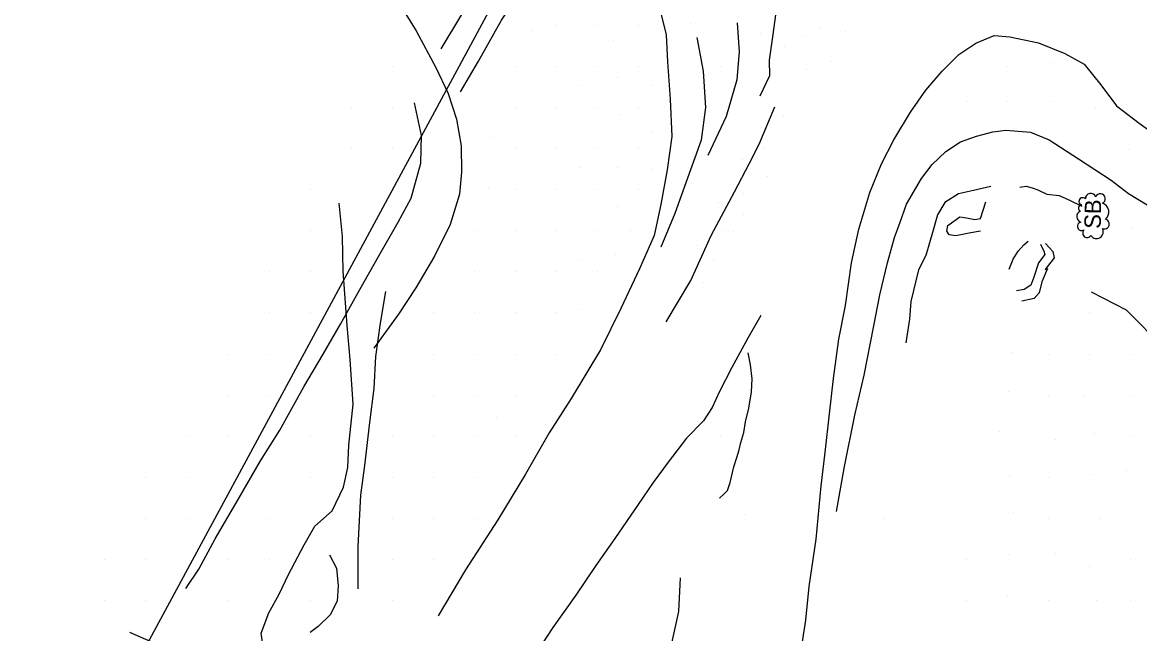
# Model space of a CAD drawing. Extents: x 19528164 to 19545171, y 7585743 to 7602745.
# Drawn here: x 19530420 to 19530964, y 7590664 to 7590962 of the extents above; entities that cross this region are included whole.
import ezdxf

# ---------------------------------------------------------------- set-up
doc = ezdxf.new("R2010")
doc.units = 0
for name, color, linetype in [('Default', 7, 'Continuous'), ('PhoBreakLine', 7, 'Continuous'), ('PhoISAEPoints', 7, 'Continuous'), ('PhoSurveyLimits', 7, 'Continuous'), ('PhoVegetation', 7, 'Continuous')]:
    doc.layers.add(name, color=color, linetype=linetype)

# ---------------------------------------------------------------- blocks, each defined once
blk = doc.blocks.new('SHRUB')
at = {"layer": 'Default'}
for centre, radius, start, end in [((-5.57, 5.14), 2.08, 10.5948, 214.3611), ((-0.81, 4.83), 2.81, 22.6036, 165.7836), ((3.27, 5.33), 1.59, 0.4605, 158.7839), ((6.61, 4.92), 1.8, 311.3936, 166.4114), ((-8.06, -2.12), 3.34, 125.8289, 299.2848), ((-8.82, 2.41), 2.18, 45.3455, 236.8073), ((8, 0.98), 2.6, 290.9039, 94.3687), ((-4.25, -5.95), 2.36, 157.0258, 349.7602), ((1.54, -3.45), 4.54, 220.0183, 343.6977), ((8.09, -3.71), 2.42, 204.8294, 69.8871)]:
    blk.add_arc(centre, radius, start, end, dxfattribs=at)
blk.add_text('SB', height=7.998, dxfattribs=at).set_placement((-6.62, -4.17))

msp = doc.modelspace()

# ---------------------------------------------------------------- linework, layer by layer
at = {"layer": 'PhoBreakLine'}
for points in [[(19530550.69, 7591170.8), (19530563.11, 7591162.21), (19530580.92, 7591148.29), (19530600.48, 7591130.16), (19530614.58, 7591114.45), (19530632.27, 7591092.51), (19530647.29, 7591073.38), (19530663.97, 7591052.42), (19530667.84, 7591042.43), (19530667.95, 7591034.18), (19530664.24, 7591022.5), (19530658.51, 7591010.63), (19530652.31, 7591000.06), (19530644.25, 7590984.42), (19530633.83, 7590965.38), (19530623.69, 7590948.7)], [(19530633.29, 7590927.79), (19530642.08, 7590942.64), (19530653.35, 7590962.66), (19530665.41, 7590981.02), (19530675.99, 7591000.09), (19530684.57, 7591014.52), (19530690.6, 7591025.66), (19530690.6, 7591025.66), (19530692.67, 7591034.39), (19530690.91, 7591042.02), (19530686.94, 7591051.91), (19530679.36, 7591060.62), (19530675.4, 7591066.27), (19530666.86, 7591077.03), (19530659.34, 7591087.61), (19530652.15, 7591095.26), (19530643.55, 7591105.89), (19530630.63, 7591119.04), (19530620.41, 7591129.76), (19530611.11, 7591138.96)], [(19530692.67, 7591034.39), (19530699.87, 7591027.21), (19530709.28, 7591011.65), (19530721.4, 7590989.7), (19530729.65, 7590971.15), (19530733.63, 7590955.63), (19530734.22, 7590942.42), (19530735.5, 7590924.2), (19530736.34, 7590906.03), (19530734.16, 7590889.81), (19530731, 7590872.82), (19530727.68, 7590857.77), (19530720.64, 7590841.48), (19530711.53, 7590822.22), (19530701.58, 7590802.09), (19530687.32, 7590778.37), (19530676.57, 7590761.63), (19530665.03, 7590741.43), (19530651.51, 7590719.23), (19530635.74, 7590694.91), (19530622.44, 7590672.51)], [(19530603.02, 7590971.6), (19530611.71, 7590957.55), (19530621.26, 7590939.63), (19530627.37, 7590926.96), (19530631.44, 7590914.42), (19530633.66, 7590901.52), (19530633.81, 7590888.67), (19530632.93, 7590877.92), (19530628.32, 7590863.06), (19530620.65, 7590847.69), (19530611.64, 7590832.33), (19530603.13, 7590819.45), (19530591.06, 7590802.78)], [(19530786.93, 7590965.34), (19530785.58, 7590955.69), (19530783.89, 7590943.27), (19530783.93, 7590935.51), (19530779.32, 7590925.7)], [(19530754.12, 7590896.86), (19530763, 7590915.96), (19530768.21, 7590933.75), (19530769.36, 7590947.2), (19530768.39, 7590961.41)], [(19530748.62, 7590954.23), (19530751.66, 7590937.8), (19530752.84, 7590920.14), (19530750.62, 7590904.23), (19530747.63, 7590895.58), (19530744.06, 7590885.65), (19530737.75, 7590868.44), (19530730.99, 7590852.13)], [(19530801.67, 7590670.26), (19530803.32, 7590686.66), (19530806.75, 7590709.84), (19530809.24, 7590735.8), (19530811.13, 7590752.07), (19530813.26, 7590770.88), (19530815.11, 7590788.12), (19530817.73, 7590807.17), (19530821.01, 7590823.57), (19530823.98, 7590844.49), (19530827.55, 7590860.78), (19530832.89, 7590878.68), (19530838.55, 7590892.74), (19530844.52, 7590904.43), (19530852.63, 7590917.85), (19530860.23, 7590928.59), (19530868.18, 7590937.88), (19530876.22, 7590945.95), (19530884.51, 7590951.51), (19530893.52, 7590955.16), (19530901.17, 7590954.53), (19530915.14, 7590951.61), (19530927.98, 7590946.47), (19530937.44, 7590941.18), (19530945.56, 7590931.19), (19530953.13, 7590920.9), (19530964.13, 7590912.57), (19530975.99, 7590904.09)], [(19530499.44, 7590685.8), (19530505.76, 7590695.14), (19530513.81, 7590710), (19530525.03, 7590729.1), (19530535.88, 7590747.99), (19530545.23, 7590762.95), (19530557.05, 7590783.96), (19530566.32, 7590799.91), (19530574.83, 7590814.55), (19530584.21, 7590831.49), (19530593.42, 7590847.47), (19530602.92, 7590864.28), (19530609.26, 7590875.91), (19530614.07, 7590893.07), (19530614.38, 7590906.42), (19530610.94, 7590922.47)], [(19530733.61, 7590815.67), (19530745.69, 7590835.86), (19530755.61, 7590857.82), (19530766.91, 7590879.08), (19530774.15, 7590892.97), (19530778.96, 7590902.18), (19530786.56, 7590920.5)], [(19530816.59, 7590723.23), (19530820.58, 7590745.21), (19530825.54, 7590770.15), (19530830.14, 7590789.72), (19530834.86, 7590813.79), (19530837.77, 7590828.8), (19530841.53, 7590844.47), (19530844.83, 7590856.84), (19530847.71, 7590864.21), (19530850.81, 7590872.95), (19530858.06, 7590885.57), (19530863.23, 7590892.36), (19530869.89, 7590898.62), (19530877.05, 7590903.34), (19530884.94, 7590906.2), (19530892.89, 7590908.35), (19530899.15, 7590909.14), (19530911.25, 7590908.18), (19530920.26, 7590904.3), (19530934.68, 7590895.09), (19530950.49, 7590884.76), (19530959.02, 7590878.21), (19530968.04, 7590872.67)], [(19530891.82, 7590881.61), (19530883.36, 7590879.75), (19530876.13, 7590878.01), (19530869.39, 7590873.91), (19530865.95, 7590867.8), (19530863.41, 7590859.2), (19530860.19, 7590847.99), (19530856.65, 7590841.02), (19530852.82, 7590825.57), (19530852.16, 7590816.92), (19530850.42, 7590805.38)], [(19530906.01, 7590881.29), (19530909.06, 7590881.78), (19530911.95, 7590881), (19530914.71, 7590880.03), (19530919.14, 7590877.96), (19530925.14, 7590877.24), (19530929.87, 7590875.16), (19530936.18, 7590872.08)], [(19530472.05, 7590664.5), (19530496.5, 7590653.83), (19530522.37, 7590642.56), (19530534.31, 7590636.88), (19530537.81, 7590638.52), (19530537.87, 7590646.74), (19530537.41, 7590655.3), (19530536.22, 7590663.95), (19530539.98, 7590673.97), (19530544.88, 7590683.06), (19530549.56, 7590692.64), (19530557.15, 7590706.97), (19530562.37, 7590716.2), (19530570.71, 7590723.65), (19530576.39, 7590735.16), (19530578.47, 7590744.68), (19530578.98, 7590755.65), (19530580.97, 7590775.5), (19530579.51, 7590797.29), (19530578.04, 7590813.85), (19530576.14, 7590840.39), (19530575.81, 7590857.29), (19530574.2, 7590873.5)], [(19530886.78, 7590859.92), (19530882.12, 7590859.11), (19530874.88, 7590857.56), (19530871.63, 7590858.16), (19530870.47, 7590859.85), (19530870.91, 7590862.7), (19530876.69, 7590866.86), (19530880.07, 7590866.4), (19530884.02, 7590865.54), (19530886.88, 7590866.02), (19530889.44, 7590874.19)], [(19530900.86, 7590841.42), (19530902.74, 7590846.18), (19530905.18, 7590850.16), (19530908.01, 7590853.16), (19530910.08, 7590855)], [(19530916.09, 7590853.48), (19530917.75, 7590850.13), (19530918.18, 7590848.53), (19530915.17, 7590844.45), (19530912.9, 7590837.44), (19530911.43, 7590833.55), (19530908.15, 7590831.37), (19530904.37, 7590830.75)], [(19530918.5, 7590853.79), (19530922.11, 7590849.96), (19530922.77, 7590846.85), (19530918.4, 7590841.11), (19530919.49, 7590841.64), (19530916.66, 7590835.16), (19530915.41, 7590829.85), (19530912.93, 7590827.06), (19530906.95, 7590825.82)], [(19530583.5, 7590685.54), (19530583.41, 7590706.2), (19530584.73, 7590731.24), (19530586.68, 7590745.74), (19530589.21, 7590766.61), (19530591.21, 7590783.27), (19530592.06, 7590798.72), (19530594.32, 7590815.05), (19530596.92, 7590830.46)], [(19531035.5, 7590764.34), (19531026.19, 7590766.39), (19531016.54, 7590767.97), (19531003.91, 7590780.8), (19530987.01, 7590792.31), (19530976.29, 7590802.81), (19530958.03, 7590821.4), (19530940.9, 7590830.2)], [(19530779.73, 7590818.76), (19530773.38, 7590807.65), (19530765.55, 7590793.47), (19530759.57, 7590781.69), (19530756.09, 7590773.95), (19530751.81, 7590767.51), (19530743.58, 7590758.93), (19530734.53, 7590747.29), (19530727.23, 7590737.32), (19530719.97, 7590726.6), (19530708.53, 7590710.06), (19530699.3, 7590696.98), (19530689.55, 7590682.46), (19530678.29, 7590666.73), (19530666.58, 7590648.88), (19530659.86, 7590637.55), (19530649.16, 7590621.32), (19530640.47, 7590607.74), (19530634.02, 7590598.94), (19530629.94, 7590592.35)], [(19530759.64, 7590729.71), (19530762.03, 7590731.99), (19530763.56, 7590733.47), (19530764.79, 7590737.45), (19530766.62, 7590745.06), (19530768.1, 7590749.58), (19530769.16, 7590753.35), (19530770.06, 7590756.92), (19530771.52, 7590761.8), (19530772.31, 7590767), (19530773.95, 7590773.58), (19530775.25, 7590781.51), (19530775.6, 7590787.86), (19530774.68, 7590794.73), (19530773.55, 7590800.54)], [(19530569.51, 7590702.18), (19530572.88, 7590695.65), (19530573.68, 7590687.08), (19530573.2, 7590679.6), (19530569.75, 7590672.85), (19530563.98, 7590667.23), (19530560.14, 7590664.31)], [(19530740.41, 7590690.97), (19530739.56, 7590674.49), (19530735.06, 7590653.92), (19530730.27, 7590630.96), (19530731.29, 7590617.33), (19530725.89, 7590603.2)], [(19530784.11, 7590544.81), (19530786.63, 7590559.36), (19530788.16, 7590575.53), (19530790.68, 7590595.15), (19530792.45, 7590612.35), (19530793.68, 7590621.33), (19530795.39, 7590631.21), (19530798.07, 7590647.25), (19530801.67, 7590670.26)]]:
    msp.add_lwpolyline(points, dxfattribs=at)
at = {"layer": 'PhoISAEPoints'}
for p, q in [((19530680, 7590960), (19530680, 7590960)), ((19530700, 7590960), (19530700, 7590960)), ((19530720, 7590960), (19530720, 7590960)), ((19530745.29, 7590960.93), (19530745.29, 7590960.93)), ((19530808.95, 7590958.84), (19530808.95, 7590958.84)), ((19530667.88, 7590957.67), (19530667.88, 7590957.67)), ((19530707.69, 7590952.61), (19530707.69, 7590952.61)), ((19530779.5, 7590956.29), (19530779.5, 7590956.29)), ((19530799.91, 7590954.68), (19530799.91, 7590954.68)), ((19530820.88, 7590957.39), (19530820.88, 7590957.39)), ((19530791.29, 7590949.84), (19530791.29, 7590949.84)), ((19530814.39, 7590942.54), (19530814.39, 7590942.54)), ((19530920.79, 7590942.02), (19530920.79, 7590942.02)), ((19530600, 7590940), (19530600, 7590940)), ((19530660, 7590940), (19530660, 7590940)), ((19530680, 7590940), (19530680, 7590940)), ((19530700, 7590940), (19530700, 7590940)), ((19530720, 7590940), (19530720, 7590940)), ((19530760, 7590940), (19530760, 7590940)), ((19530802.06, 7590938.41), (19530802.06, 7590938.41)), ((19530900, 7590940), (19530900, 7590940)), ((19530692.56, 7590930.61), (19530692.56, 7590930.61)), ((19530710.01, 7590934.89), (19530710.01, 7590934.89)), ((19530726.47, 7590930.64), (19530726.47, 7590930.64)), ((19530580, 7590920), (19530580, 7590920)), ((19530600, 7590920), (19530600, 7590920)), ((19530660, 7590920), (19530660, 7590920)), ((19530680, 7590920), (19530680, 7590920)), ((19530700, 7590920), (19530700, 7590920)), ((19530720, 7590920), (19530720, 7590920)), ((19530880.71, 7590923.15), (19530880.71, 7590923.15)), ((19530900.22, 7590922.81), (19530900.22, 7590922.81)), ((19530922.47, 7590923.13), (19530922.47, 7590923.13)), ((19530942.65, 7590919.95), (19530942.65, 7590919.95)), ((19530711.02, 7590916.52), (19530711.02, 7590916.52)), ((19530790.66, 7590915.5), (19530790.66, 7590915.5)), ((19530649.31, 7590905.74), (19530649.31, 7590905.74)), ((19530726.65, 7590908.42), (19530726.65, 7590908.42)), ((19530580, 7590900), (19530580, 7590900)), ((19530600, 7590900), (19530600, 7590900)), ((19530660, 7590900), (19530660, 7590900)), ((19530680, 7590900), (19530680, 7590900)), ((19530700, 7590900), (19530700, 7590900)), ((19530720, 7590900), (19530720, 7590900)), ((19530781.59, 7590900.25), (19530781.59, 7590900.25)), ((19530958.87, 7590899.54), (19530958.87, 7590899.54)), ((19530770.6, 7590894.72), (19530770.6, 7590894.72)), ((19530692.05, 7590890.76), (19530692.05, 7590890.76)), ((19530709.76, 7590890.69), (19530709.76, 7590890.69)), ((19530726.78, 7590890.05), (19530726.78, 7590890.05)), ((19530783.1, 7590886.63), (19530783.1, 7590886.63)), ((19530560, 7590880), (19530560, 7590880)), ((19530600, 7590880), (19530600, 7590880)), ((19530646.78, 7590880.53), (19530646.78, 7590880.53)), ((19530660, 7590880), (19530660, 7590880)), ((19530680, 7590880), (19530680, 7590880)), ((19530700, 7590880), (19530700, 7590880)), ((19530720, 7590880), (19530720, 7590880)), ((19530771.06, 7590878.41), (19530771.06, 7590878.41)), ((19530709.72, 7590871.91), (19530709.72, 7590871.91)), ((19530758.93, 7590873.75), (19530758.93, 7590873.75)), ((19530771.37, 7590867.98), (19530771.37, 7590867.98)), ((19530560, 7590860), (19530560, 7590860)), ((19530640, 7590860), (19530640, 7590860)), ((19530660, 7590860), (19530660, 7590860)), ((19530680, 7590860), (19530680, 7590860)), ((19530700, 7590860), (19530700, 7590860)), ((19530716.14, 7590860.04), (19530716.14, 7590860.04)), ((19530760.91, 7590860.16), (19530760.91, 7590860.16)), ((19530960.79, 7590860.97), (19530960.79, 7590860.97)), ((19530766.54, 7590859.54), (19530766.54, 7590859.54)), ((19530748.47, 7590852.64), (19530748.47, 7590852.64)), ((19530692.39, 7590845.62), (19530692.39, 7590845.62)), ((19530709.08, 7590848.39), (19530709.08, 7590848.39)), ((19530756.66, 7590845.53), (19530756.66, 7590845.53)), ((19530540, 7590840), (19530540, 7590840)), ((19530560, 7590840), (19530560, 7590840)), ((19530640, 7590840), (19530640, 7590840)), ((19530660, 7590840), (19530660, 7590840)), ((19530680, 7590840), (19530680, 7590840)), ((19530700, 7590840), (19530700, 7590840)), ((19530751.62, 7590834.74), (19530751.62, 7590834.74)), ((19530690.67, 7590821.73), (19530690.67, 7590821.73)), ((19530540, 7590820), (19530540, 7590820)), ((19530560, 7590820), (19530560, 7590820)), ((19530620, 7590820), (19530620, 7590820)), ((19530640, 7590820), (19530640, 7590820)), ((19530660, 7590820), (19530660, 7590820)), ((19530680, 7590820), (19530680, 7590820)), ((19530940, 7590820), (19530940, 7590820)), ((19530520, 7590800), (19530520, 7590800)), ((19530540, 7590800), (19530540, 7590800)), ((19530620, 7590800), (19530620, 7590800)), ((19530640, 7590800), (19530640, 7590800)), ((19530660, 7590800), (19530660, 7590800)), ((19530680, 7590800), (19530680, 7590800)), ((19530901.85, 7590800.82), (19530901.85, 7590800.82)), ((19530920, 7590800), (19530920, 7590800)), ((19530940, 7590800), (19530940, 7590800)), ((19530960, 7590800), (19530960, 7590800)), ((19530520, 7590780), (19530520, 7590780)), ((19530540, 7590780), (19530540, 7590780)), ((19530620, 7590780), (19530620, 7590780)), ((19530640, 7590780), (19530640, 7590780)), ((19530660, 7590780), (19530660, 7590780)), ((19530900.35, 7590781.84), (19530900.35, 7590781.84)), ((19530920, 7590780), (19530920, 7590780)), ((19530937.53, 7590779.5), (19530937.53, 7590779.5)), ((19530960, 7590780), (19530960, 7590780)), ((19530651.06, 7590768.99), (19530651.06, 7590768.99)), ((19530895.96, 7590762.26), (19530895.96, 7590762.26)), ((19530500, 7590760), (19530500, 7590760)), ((19530520, 7590760), (19530520, 7590760)), ((19530560, 7590760), (19530560, 7590760)), ((19530600, 7590760), (19530600, 7590760)), ((19530620, 7590760), (19530620, 7590760)), ((19530640, 7590760), (19530640, 7590760)), ((19530660, 7590760), (19530660, 7590760)), ((19530760, 7590760), (19530760, 7590760)), ((19530923.37, 7590758.46), (19530923.37, 7590758.46)), ((19530942.49, 7590761.38), (19530942.49, 7590761.38)), ((19530960, 7590760), (19530960, 7590760)), ((19530480, 7590740), (19530480, 7590740)), ((19530500, 7590740), (19530500, 7590740)), ((19530560, 7590740), (19530560, 7590740)), ((19530600, 7590740), (19530600, 7590740)), ((19530620, 7590740), (19530620, 7590740)), ((19530640, 7590740), (19530640, 7590740)), ((19530900.9, 7590740.68), (19530900.9, 7590740.68)), ((19530920, 7590740), (19530920, 7590740)), ((19530940.44, 7590741.39), (19530940.44, 7590741.39)), ((19530958, 7590743.41), (19530958, 7590743.41)), ((19530480, 7590720), (19530480, 7590720)), ((19530500, 7590720), (19530500, 7590720)), ((19530540, 7590720), (19530540, 7590720)), ((19530600, 7590720), (19530600, 7590720)), ((19530620, 7590720), (19530620, 7590720)), ((19530640, 7590720), (19530640, 7590720)), ((19530771.69, 7590722.04), (19530771.69, 7590722.04)), ((19530840, 7590720), (19530840, 7590720)), ((19530902.88, 7590722.69), (19530902.88, 7590722.69)), ((19530920, 7590720), (19530920, 7590720)), ((19530945.11, 7590719.85), (19530945.11, 7590719.85)), ((19530900.33, 7590702.31), (19530900.33, 7590702.31)), ((19530923.39, 7590702.66), (19530923.39, 7590702.66)), ((19530460, 7590700), (19530460, 7590700)), ((19530480, 7590700), (19530480, 7590700)), ((19530520, 7590700), (19530520, 7590700)), ((19530540, 7590700), (19530540, 7590700)), ((19530600, 7590700), (19530600, 7590700)), ((19530620, 7590700), (19530620, 7590700)), ((19530880, 7590700), (19530880, 7590700)), ((19530939.99, 7590696.63), (19530939.99, 7590696.63)), ((19530960, 7590700), (19530960, 7590700)), ((19530460, 7590680), (19530460, 7590680)), ((19530480, 7590680), (19530480, 7590680)), ((19530520, 7590680), (19530520, 7590680)), ((19530560, 7590680), (19530560, 7590680)), ((19530600, 7590680), (19530600, 7590680)), ((19530880, 7590680), (19530880, 7590680)), ((19530900.17, 7590682.45), (19530900.17, 7590682.45)), ((19530920, 7590680), (19530920, 7590680)), ((19530943.42, 7590680.13), (19530943.42, 7590680.13)), ((19530960, 7590680), (19530960, 7590680))]:
    msp.add_line(p, q, dxfattribs=at)
at = {"layer": 'PhoSurveyLimits'}
msp.add_lwpolyline([(19530813.08, 7588141.83), (19530826.36, 7590306.58), (19530836.02, 7590358.63), (19530806.78, 7590373.28), (19530757.47, 7590370.26), (19530695.18, 7590346.98), (19530641.2, 7590285.01), (19530612.99, 7590219.54), (19530561.32, 7590123.06), (19530451.92, 7590109.87), (19530349.02, 7590108.43), (19530203.76, 7589978.43), (19530164.76, 7590012.57), (19530344.64, 7590385.93), (19530300.57, 7590416.51), (19530480.77, 7590658.88), (19530687.59, 7591041.97), (19530295.19, 7591473.06), (19529551.78, 7591996.95)], dxfattribs=at)

# ---------------------------------------------------------------- block references
at = {"layer": 'PhoVegetation', "xscale": 0.9999999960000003, "yscale": 0.9999999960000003, "rotation": 88.89301078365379}
msp.add_blockref('SHRUB', (19530941.4, 7590867.69), dxfattribs=at)

doc.saveas('drawing.dxf')
